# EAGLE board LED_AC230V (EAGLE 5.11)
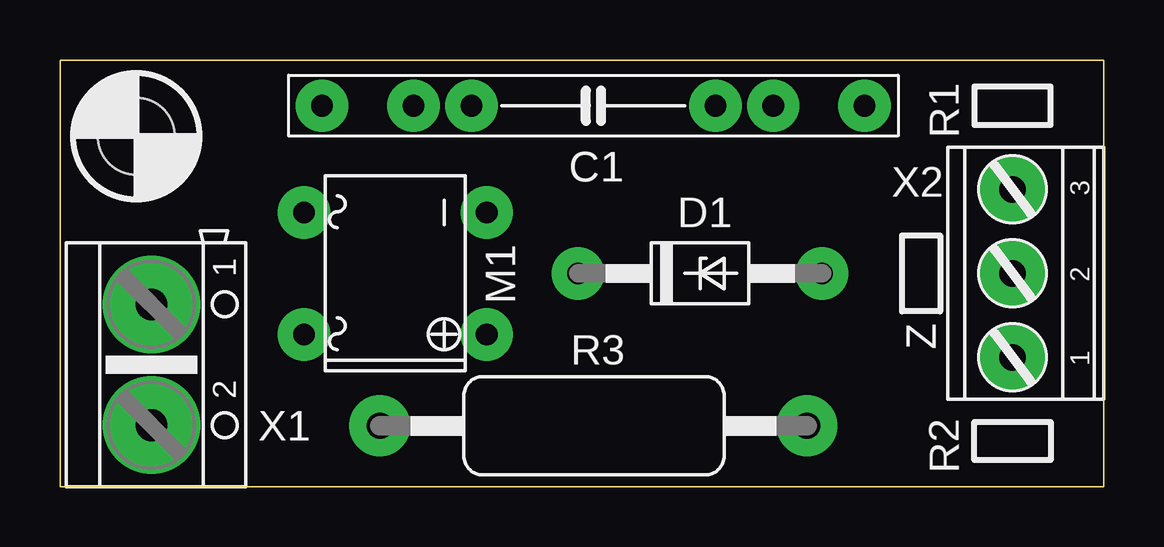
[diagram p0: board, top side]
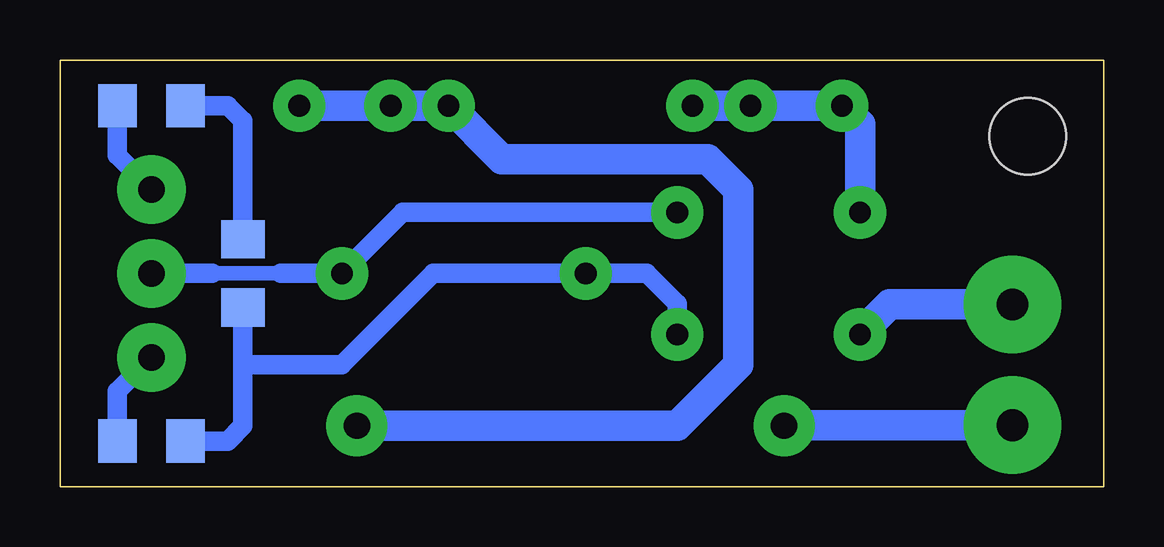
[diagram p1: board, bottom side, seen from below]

Size 43.5 x 17.78 mm. Coordinates in mm from the lower left corner, seen from the top.
Outline: 0,17.78 0,0 43.5,0 43.5,17.78 0,17.78
Copper layers (1*16): Top 0.035mm / dielectric 1.5mm / Bottom 0.035mm
Design rules "AVT": minimum track width 16mil, minimum drill 19mil, track to track 10mil, track to pad 10mil, pad to pad 10mil, via to via 10mil, smd to smd 10mil, copper to edge 20mil, drill to drill 10mil, minimum pad ring 10mil, minimum via ring 10mil, stop-mask expansion 4mil, vias tented up to drill 0mil, thermal gap 10mil
Holes 3.2 mm at 3.17,14.61

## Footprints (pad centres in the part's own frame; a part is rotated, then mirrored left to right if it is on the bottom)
C225_150_102_M = drill 0.9 pad 2.184 round: 1 -11.303,0; 2 11.303,0; 3 -7.493,0; 4 7.493,0; 5 -5.08,0; 6 5.08,0
DO41Z10 = drill 0.9 pad 2.184 round: A 5.08,0; C -5.08,0
B-DIL = drill 0.9 pad 2.184 round: + -2.54,-3.81; - 2.54,-3.81; AC1 2.54,3.81; AC2 -2.54,3.81
R1206_TOP/BOT = smd 1.6 x 1.803 bottom: 1 -1.422,0; 2 1.422,0
AC01 = drill 1.1 pad 2.54 round: 1 -8.9,0; 2 8.9,0
AK500/2 = drill 1.321 pad 4.064 round: 1 -2.515,0; 2 2.515,0
AK550/3 = drill 1.1 pad 2.857 round: 1 -3.5,0; 2 0,0; 3 3.5,0

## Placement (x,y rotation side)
C1  [C225_150_102_M]  22.23,15.88 180 top
D1  [DO41Z10]  26.67,8.89 0 top
M1  [B-DIL]  13.97,8.89 90 top
R1  [R1206_TOP/BOT]  39.69,15.88 180 top
R2  [R1206_TOP/BOT]  39.69,1.91 180 top
R3  [AC01]  22.23,2.54 0 top
X1  [AK500/2]  3.81,5.08 270 top
X2  [AK550/3]  39.69,8.89 90 top
Z  [R1206_TOP/BOT]  35.88,8.89 270 top

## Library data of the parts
C1 R1 R2 Z = rcl
D1 = diode
M1 = rectifier
R3 = resistor-power; OC_FARNELL: unknown; OC_NEWARK: unknown
X1 = con-ptr500; OC_FARNELL: unknown; OC_NEWARK: unknown
X2 = con-ptr500+

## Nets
N$1: R2.1 X2.1
N$2: C1.1 C1.3 C1.5 R3.2
N$3: R1.1 X2.3
N$4: R3.1 X1.2
N$5: R1.2 Z.1
N$6: D1.C M1.+ R2.2 Z.2
N$7: M1.AC2 X1.1
N$12: D1.A M1.- X2.2
N$16: C1.2 C1.4 C1.6 M1.AC1

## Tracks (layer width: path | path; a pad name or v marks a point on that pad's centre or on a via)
N$1
  Bottom 0.813: R2.1 41.11,3.97 X2.1
N$2
  Bottom 1.27: C1.1 C1.3 C1.5 25.08,13.65 16.51,13.65 15.24,12.38 15.24,5.08 17.78,2.54 R3.2
N$3
  Bottom 0.813: R1.1 41.11,13.81 X2.3
N$4
  Bottom 1.27: X1.2 13.3,2.56 R3.1
N$5
  Bottom 0.813: Z.1 35.88,15.24 36.51,15.88 R1.2
N$6
  Bottom 0.813: M1.+ 17.78,7.62 19.05,8.89 D1.C 27.94,8.89 31.75,5.08 35.88,5.08 | R2.2 36.51,1.91 35.88,2.54 35.88,5.08 | 35.88,5.08 Z.2
N$7
  Bottom 1.27: X1.1 8.91,7.59 M1.AC2
N$12
  Bottom 0.61: 34.29,8.89 37.15,8.89
  Bottom 0.813: M1.- 29.21,11.43 D1.A 34.29,8.89 | 37.15,8.89 X2.2
N$16
  Bottom 1.27: M1.AC1 10.16,15.11 C1.2 C1.4 C1.6

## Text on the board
bStop: + | WB | - | K | + | AC | RGY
